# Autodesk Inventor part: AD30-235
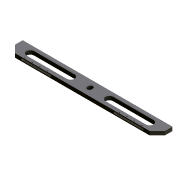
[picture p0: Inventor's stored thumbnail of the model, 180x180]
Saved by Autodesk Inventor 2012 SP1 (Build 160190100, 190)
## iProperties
Shininess: 0.0
Length Units: 11269
Angle Units: 11279
Time Units: 11290
Mass Units: 11283
Length Display Precision: 3
Angle Display Precision: 2
Compacted: True
Created: 2000-06
Part Number: AD30-235
Project: BONDING PRESS
User Status: RELEASED
Description: STIFFENER
Document SubType Name: Modeling
Designer: Ron
Material: Aluminum-6061-AHC
Density: 1 g/cm^3
Density: 0.0
Volumn: 0.0
Area: 0.0
PropertySet Name: Model Information
Control State: 0
Master: False
Checked Out: False
Title: STIFFENER
Author: Ron
Revision Number: A
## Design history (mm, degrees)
node "Extrusion1" dims "d2" = 50.8, "d3" = 0
  sketch "Sketch1"
    geometry: L1 (-250, -6.35)-(250, -6.35); L2 (250, -6.35)-(250, 6.35); L3 (250, 6.35)-(-250, 6.35); L4 (-250, 6.35)-(-250, -6.35); L5 (-250, -6.35)-(250, 6.35); 2 further points
    constraints: 10 end point, 2 parallel, 1 coincident, 1 horizontal, 1 midpoint, 1 perpendicular
    dimensions: "d0" = 12.7 distance between parallel lines of L3 L1; "d1" = 500 distance of L1.start L1.end
node "Chamfer1" dims "d4" = 25.4, "d5" = 25.4, "d52" = 45 deg
node "Extrusion2" dims "d11" = 10, "d12" = 0
  sketch "Sketch2"
    geometry: L1 (185.3, 38.1)-(50.7, 38.1); L2 (50.7, 38.1)-(50.7, 12.7); L3 (50.7, 12.7)-(185.3, 12.7); L4 (185.3, 12.7)-(185.3, 38.1); L5 (250, 25.4)-(185.3, 25.4); A1 r 12.7 centre (185.3, 25.4) between (185.3, 12.7) and (185.3, 38.1); A2 r 12.7 centre (50.7, 25.4) between (50.7, 38.1) and (50.7, 12.7)
    constraints: 10 end point, 4 point on circle, 4 tangent, 2 centre point, 2 horizontal, 2 parallel, 1 midpoint, 1 perpendicular
    dimensions: "d9" = 134.6 distance of L1.start L1.end; "d56" = 64.7 distance from line of L4 L5.start; "d57" = 25.4 distance of L1.end L2.end
node "Hole1" dims "d17" = 3.242, "d18" = 4, "d19" = 2, "d20" = 60 deg, "d21" = 8, "d22" = 118 deg, "d50" = 6
  sketch "Sketch3"
    geometry: L1 (250, 6.35)-(250, -6.35) reference; L2 (-250, 6.35)-(250, 6.35) reference; L3 (250, 0)-(-98.953, 0); 3 further points
    constraints: 3 point on line, 2 end point, 1 midpoint, 1 parallel
    dimensions: "d14" = 30 distance from line of L1 point (220, 0); "d15" = 80 distance of point (140, 0) point (220, 0); "d16" = 80 distance of point (60, 0) point (140, 0)
node "Hole2" dims "d23" = 3.242, "d24" = 4, "d25" = 2, "d26" = 60 deg, "d27" = 8, "d28" = 118 deg, "d51" = 6
  sketch "Sketch4"
    geometry: L1 (474.6, 50.8)-(25.4, 50.8) reference; L2 (500, 0)-(500, 25.4) reference; L3 (235, 36.075)-(235, 17.025); 1 further point
    constraints: 2 end point, 1 parallel
    dimensions: "d53" = 19.05 distance of L3.start L3.end; "d54" = 15 horizontal distance of point (250, 25.4) L3.end; "d55" = 14.725 distance from line of L1 L3.start
node "Extrusion3" dims "d32" = 10, "d33" = 0
  sketch "Sketch5"
    geometry: L1 (474.6, 50.8)-(25.4, 50.8) reference; L2 (0, 0)-(0, 25.4) reference; C1 r 1.587 at (55, 47.8)
    constraints: 1 centre point
    dimensions: "d29" = 3.175 diameter of C1; "d30" = 3 distance from line of L1 C1.centre; "d31" = 55 distance from line of L2 C1.centre
node "Rectangular Pattern1" dims "d41" = 40, "d43" = 25
workaxis "Work Axis1"
node "Extrusion4" dims "d36" = 12, "d37" = 0
  sketch "Sketch6"
    geometry: L1 (-195, -8.89)-(-195, 8.89) reference; L2 (-201.35, -3.175)-(-107.7, -3.175); L3 (-107.7, -3.175)-(-107.7, 3.175); L4 (-107.7, 3.175)-(-201.35, 3.175); L5 (-201.35, 3.175)-(-201.35, -3.175); L6 (-224.6, -6.35)-(-224.6, 6.35) reference; A1 r 3.175 centre (-107.7, 0) between (-107.7, -3.175) and (-107.7, 3.175); A2 r 3.175 centre (-201.35, 0) between (-201.35, 3.175) and (-201.35, -3.175); 2 further points
    constraints: 8 end point, 4 point on circle, 4 tangent, 2 centre point, 2 midpoint, 2 parallel, 1 horizontal, 1 horizontal alignment, 1 perpendicular
    dimensions: "d34" = 6.35 distance from line of L4 L2.start; "d39" = 6.35 distance from line of L4.end L1; "d40" = 93.65 distance of L3.end L4.end
node "Extrusion5" dims "d46" = 10, "d47" = 0
  sketch "Sketch7"
    geometry: L1 (500, 0)-(500, 25.4) reference; L2 (242.856, 27.4)-(242.856, 23.4); L3 (257.144, 23.4)-(257.144, 27.4); C1 r 7.144 at (250, 25.4); A1 r 7.144 centre (250, 23.4) between (242.856, 23.4) and (257.144, 23.4); A2 r 7.144 centre (250, 27.4) between (257.144, 27.4) and (242.856, 27.4); 1 further point
    constraints: 6 tangent, 4 end point, 4 point on circle, 3 centre point, 1 coincident, 1 parallel, 1 vertical alignment
    dimensions: "d44" = 14.2875 diameter of C1; "d48" = 2 distance of A2.centre C1.centre; "d49" = 2 distance of A1.centre C1.centre
mirror "Mirror4"
body "Solid1"
